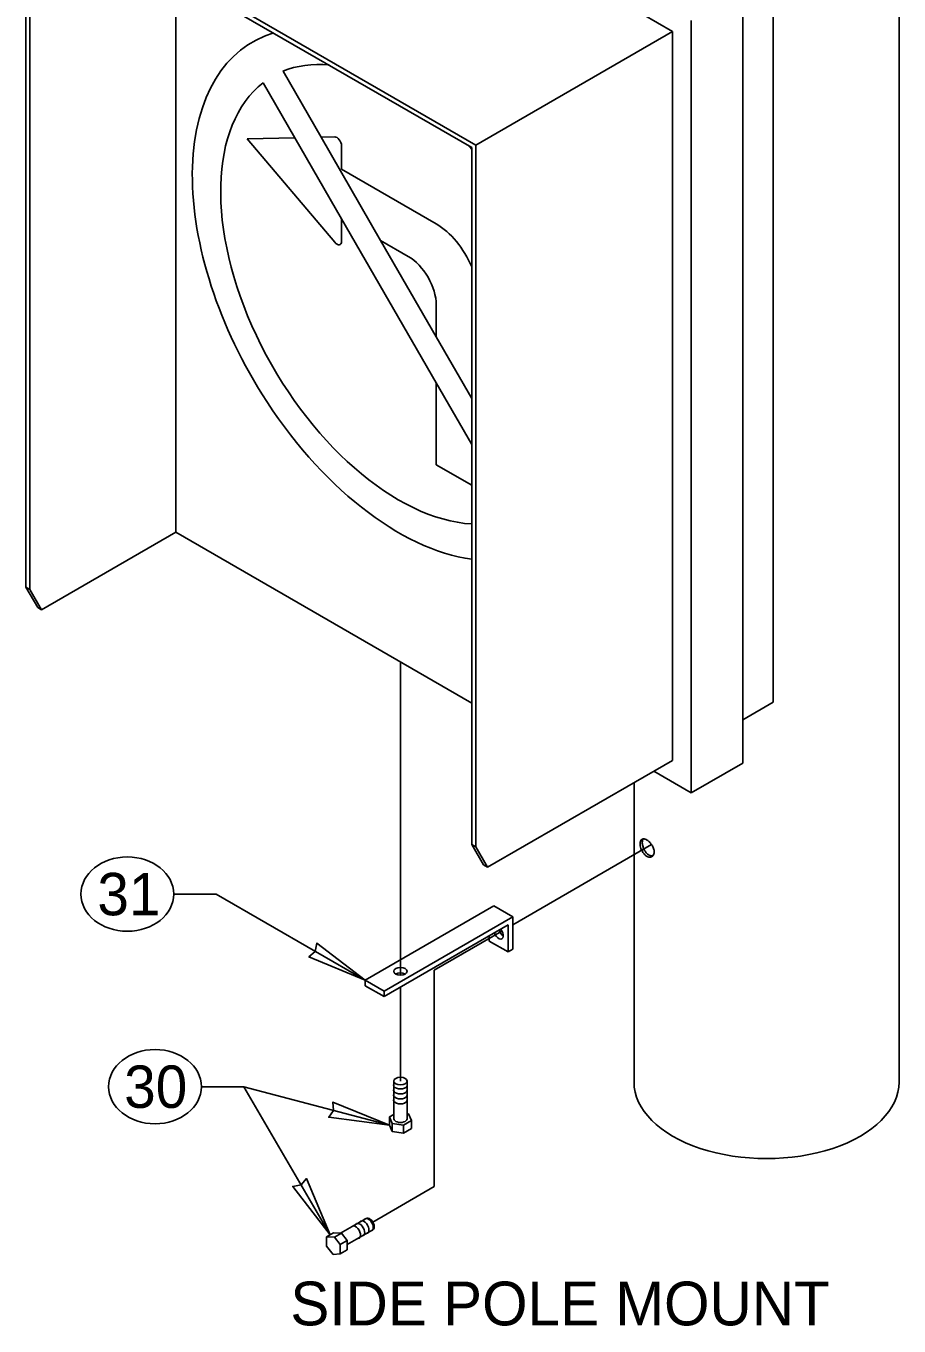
# Model space of a CAD drawing. Extents: x 99862 to 104211, y 98939 to 102076.
# Drawn here: x 101431.2 to 101760.6, y 100458.9 to 100949.2 of the extents above; entities that cross this region are included whole.
import ezdxf

# ---------------------------------------------------------------- set-up
doc = ezdxf.new("R2010")
doc.units = 0
for name, color, linetype in [('Level 1', 7, 'Continuous'), ('Level 12', 7, 'Continuous'), ('Level 15', 7, 'Continuous'), ('Level 20', 7, 'Continuous'), ('Level 22', 7, 'Continuous'), ('Level 27', 7, 'Continuous'), ('Level 31', 7, 'Continuous'), ('Level 32', 7, 'Continuous')]:
    doc.layers.add(name, color=color, linetype=linetype)

msp = doc.modelspace()

# ---------------------------------------------------------------- linework, layer by layer
at = {"layer": 'Level 1'}
msp.add_line((101663.6, 100642.46), (101663.6, 100642.46), dxfattribs=at)
for centre, major_axis in [((101572.46, 100549.79), (2.59, 0)), ((101572.46, 100547.92), (2.59, 0)), ((101572.46, 100546.05), (2.59, 0)), ((101572.46, 100544.17), (2.59, 0)), ((101557.16, 100495.22), (-1.29, 2.24)), ((101558.78, 100496.16), (-1.29, 2.24)), ((101560.41, 100497.1), (-1.29, 2.24)), ((101555.54, 100494.28), (-1.29, 2.24))]:
    msp.add_ellipse(centre, major_axis=major_axis, ratio=0.57735, start_param=2.878526, end_param=6.548134, dxfattribs=at)
for points in [[(101665.37, 100636.09), (101665.02, 100636.3), (101664.69, 100636.58), (101664.08, 100637.28), (101663.82, 100637.69), (101663.16, 100639.01), (101662.92, 100640), (101662.92, 100641.2), (101662.98, 100641.56), (101663.21, 100642.12), (101663.38, 100642.33), (101663.82, 100642.59), (101664.08, 100642.63), (101664.69, 100642.55), (101665.03, 100642.42), (101666.06, 100641.82), (101666.8, 100641.12), (101667.62, 100639.89), (101667.84, 100639.45), (101668.14, 100638.58), (101668.22, 100638.15), (101668.23, 100637.34), (101668.15, 100636.97), (101667.84, 100636.37), (101667.62, 100636.12), (101666.81, 100635.66), (101666.07, 100635.69), (101665.37, 100636.09)], [(101664.05, 100642.6), (101663.84, 100642.29), (101663.72, 100641.82), (101663.72, 100640.87), (101663.78, 100640.42), (101664, 100639.5), (101664.17, 100639.04), (101664.61, 100638.15), (101664.88, 100637.74), (101665.48, 100637.04), (101665.82, 100636.75), (101666.69, 100636.25), (101667.24, 100636.15), (101667.71, 100636.26)]]:
    msp.add_open_spline(points, degree=3, dxfattribs=at)
at = {"layer": 'Level 12'}
for p, q in [((101760.6, 100550.89), (101760.6, 101272.27)), ((101660.6, 100663.86), (101660.6, 100550.89))]:
    msp.add_line(p, q, dxfattribs=at)
msp.add_ellipse((101710.6, 100550.89), major_axis=(50, 0), ratio=0.57735, start_param=3.141583, end_param=6.283185, dxfattribs=at)
at = {"layer": 'Level 15'}
for p, q in [((101572.46, 100591.22), (101572.46, 100709.38)), ((101667.24, 100640.45), (101614.83, 100610.21)), ((101486.91, 100621.8), (101502.91, 100621.8)), ((101559.2, 100589.3), (101502.91, 100621.8)), ((101610.76, 100607.87), (101585.21, 100593.13)), ((101585.21, 100593.13), (101585.21, 100511.5)), ((101572.46, 100551.26), (101572.46, 100586.75)), ((101497.35, 100549.16), (101513.35, 100549.16)), ((101513.35, 100549.16), (101568.28, 100534.67)), ((101513.35, 100549.16), (101545.92, 100493.29)), ((101585.21, 100511.5), (101562.04, 100498.1))]:
    msp.add_line(p, q, dxfattribs=at)
for points in [[(101559.2, 100589.3), (101537.94, 100598.13), (101540.34, 100600.19), (101540.92, 100603.3)], [(101568.28, 100534.67), (101545.44, 100537.61), (101547.22, 100540.23), (101546.96, 100543.38)], [(101545.92, 100493.29), (101531.84, 100511.51), (101534.95, 100512.1), (101537, 100514.52)]]:
    msp.add_lwpolyline(points, close=True, dxfattribs=at)
at = {"layer": 'Level 20'}
for centre in [(101469.41, 100621.8), (101479.85, 100549.16)]:
    msp.add_ellipse(centre, major_axis=(-17.5, 0), ratio=0.8, dxfattribs=at)
at = {"layer": 'Level 22'}
for p, q in [((101431.16, 101002.31), (101431.16, 100737.57)), ((101600.87, 100904.33), (101431.16, 101002.31)), ((101675.12, 100947.2), (101575.94, 101004.46)), ((101432.66, 100736.7), (101432.66, 100999.71)), ((101599.37, 100903.46), (101432.66, 100999.71)), ((101713.13, 100694.19), (101713.13, 100969.14)), ((101487.74, 100967.91), (101487.74, 100758.29)), ((101701.64, 100671.23), (101701.64, 100962.51)), ((101682.2, 100660), (101682.2, 100951.28)), ((101600.87, 100904.33), (101675.12, 100947.2)), ((101675.12, 100947.2), (101675.12, 100672.25)), ((101600.87, 100639.59), (101600.87, 100904.33)), ((101599.37, 100640.45), (101599.37, 100903.46)), ((101437.08, 100729.05), (101487.74, 100758.29)), ((101487.74, 100758.29), (101599.37, 100693.84)), ((101431.16, 100737.57), (101435.58, 100729.91)), ((101431.16, 100737.57), (101432.66, 100736.7)), ((101432.66, 100736.7), (101437.08, 100729.05)), ((101435.58, 100729.91), (101437.08, 100729.05)), ((101701.64, 100687.56), (101713.13, 100694.19)), ((101605.29, 100631.93), (101675.12, 100672.25)), ((101682.2, 100660), (101701.64, 100671.23)), ((101668.05, 100668.17), (101682.2, 100660)), ((101599.37, 100640.45), (101603.79, 100632.8)), ((101599.37, 100640.45), (101600.87, 100639.59)), ((101600.87, 100639.59), (101605.29, 100631.93)), ((101603.79, 100632.8), (101605.29, 100631.93))]:
    msp.add_line(p, q, dxfattribs=at)
at = {"layer": 'Level 27'}
for p, q in [((101542.57, 100907.34), (101528.2, 100932.22)), ((101520.61, 100927.85), (101532.61, 100907.06)), ((101532.61, 100907.06), (101514.59, 100906.63)), ((101514.59, 100906.63), (101547.67, 100867.66)), ((101550.25, 100876.51), (101532.61, 100907.06)), ((101547.67, 100907.42), (101542.57, 100907.34)), ((101564.95, 100868.37), (101542.57, 100907.34)), ((101550.25, 100895.23), (101550.25, 100904.11)), ((101585.97, 100874.6), (101550.25, 100895.23)), ((101550.25, 100867.97), (101550.25, 100876.51)), ((101550.25, 100876.51), (101585.97, 100814.63)), ((101586.06, 100874.66), (101585.97, 100874.6)), ((101549.73, 100866.83), (101549.82, 100866.88)), ((101585.97, 100831.95), (101564.95, 100868.37)), ((101564.95, 100868.37), (101575.37, 100862.36)), ((101585.97, 100843.99), (101585.97, 100831.95)), ((101599.37, 100808.75), (101585.97, 100831.95)), ((101599.37, 100791.43), (101585.97, 100814.64)), ((101585.97, 100814.63), (101585.97, 100783.75)), ((101585.97, 100783.75), (101599.37, 100776.02))]:
    msp.add_line(p, q, dxfattribs=at)
for centre, major_axis, start_param, end_param in [((101571.71, 100848), (55, -95.26), 3.007404, 4.773824), ((101571.71, 100848), (-47.5, 82.27), 5.898115, 6.204156), ((101571.8, 100848.05), (-47.5, 82.27), 0.080896, 2.779139), ((101548.48, 100905.13), (-1.25, 2.17), 3.926991, 5.977732), ((101571.71, 100848), (-47.5, 82.27), 5.073399, 5.097459), ((101585.97, 100856.23), (-11.25, 19.49), 4.496649, 5.497787), ((101548.48, 100868.99), (-1.25, 2.17), 1.87625, 3.926991), ((101575.37, 100850.11), (-7.5, 12.99), 3.926991, 5.497787), ((101571.71, 100848), (55, -95.26), 4.773824, 5.861358)]:
    msp.add_ellipse(centre, major_axis=major_axis, ratio=0.57735, start_param=start_param, end_param=end_param, dxfattribs=at)
at = {"layer": 'Level 31'}
for p, q in [((101566.27, 100585.22), (101614.83, 100613.25)), ((101613.06, 100599.99), (101613.06, 100610.19)), ((101569.96, 100551.26), (101569.96, 100537.09)), ((101574.96, 100537.09), (101574.96, 100551.26)), ((101569.96, 100538.71), (101568.28, 100537.74)), ((101568.28, 100534.67), (101568.28, 100537.74)), ((101568.28, 100537.74), (101569.4, 100535.32)), ((101573.58, 100534.67), (101576.64, 100536.44)), ((101575.52, 100538.86), (101574.96, 100538.94)), ((101576.64, 100536.44), (101575.52, 100538.86)), ((101576.64, 100533.38), (101576.64, 100536.44)), ((101568.28, 100534.67), (101569.4, 100532.26)), ((101569.4, 100532.26), (101569.4, 100535.32)), ((101569.4, 100535.32), (101573.58, 100534.67)), ((101569.4, 100532.26), (101573.58, 100531.61)), ((101573.58, 100531.61), (101573.58, 100534.67)), ((101573.58, 100531.61), (101576.64, 100533.38)), ((101549.86, 100493.89), (101559.5, 100499.45)), ((101544.59, 100492.53), (101547.25, 100494.06)), ((101544.59, 100492.53), (101544.59, 100488.99)), ((101547.59, 100492.34), (101544.59, 100492.53)), ((101550.24, 100493.87), (101547.25, 100494.06)), ((101547.59, 100492.34), (101550.24, 100493.87)), ((101547.59, 100492.34), (101549.75, 100489.65)), ((101550.24, 100493.87), (101552.4, 100491.18)), ((101552.4, 100489.59), (101562.07, 100495.17)), ((101547.1, 100485.88), (101544.59, 100488.99)), ((101549.75, 100489.65), (101552.4, 100491.18)), ((101549.75, 100489.65), (101549.75, 100486.11)), ((101549.75, 100486.11), (101552.4, 100487.65)), ((101552.4, 100491.18), (101552.4, 100487.65)), ((101549.75, 100486.11), (101547.1, 100485.88))]:
    msp.add_line(p, q, dxfattribs=at)
msp.add_ellipse((101572.46, 100551.26), major_axis=(-2.5, 0), ratio=0.57735, dxfattribs=at)
for centre, major_axis, start_param, end_param in [((101572.46, 100537.09), (-2.5, 0), 6.283185, 9.424778), ((101560.82, 100497.33), (-1.25, 2.17), 3.141593, 6.341208)]:
    msp.add_ellipse(centre, major_axis=major_axis, ratio=0.57735, start_param=start_param, end_param=end_param, dxfattribs=at)
at = {"layer": 'Level 32'}
for p, q in [((101559.2, 100589.3), (101607.76, 100617.34)), ((101607.76, 100617.34), (101614.83, 100613.25)), ((101613.06, 100610.19), (101566.27, 100583.18)), ((101614.83, 100613.25), (101614.83, 100601.01)), ((101605.99, 100604.07), (101605.99, 100606.11)), ((101605.99, 100604.07), (101613.06, 100599.99)), ((101614.83, 100601.01), (101613.06, 100599.99)), ((101559.2, 100587.26), (101559.2, 100589.3)), ((101559.2, 100589.3), (101566.27, 100585.22)), ((101559.2, 100587.26), (101566.27, 100583.18)), ((101566.27, 100583.18), (101566.27, 100585.22))]:
    msp.add_line(p, q, dxfattribs=at)
for centre, major_axis, start_param, end_param in [((101609.52, 100607.13), (1.25, -2.17), 4.351022, 8.215349), ((101611.29, 100608.15), (-1.25, 2.17), 1.209429, 2.356194), ((101572.46, 100590.63), (2.5, 0), 0.785398, 2.356194)]:
    msp.add_ellipse(centre, major_axis=major_axis, ratio=0.57735, start_param=start_param, end_param=end_param, dxfattribs=at)
msp.add_ellipse((101572.46, 100592.67), major_axis=(-2.5, 0), ratio=0.57735, dxfattribs=at)

# ---------------------------------------------------------------- texts
at = {"layer": 'Level 20'}
for s, height, p in [('31', 16, (101458.09, 100613.8)), ('30', 16, (101468.22, 100541.16)), ('SIDE POLE MOUNT', 16.5, (101530.92, 100459.13))]:
    msp.add_text(s, height=height, dxfattribs=at).set_placement(p)

doc.saveas('drawing.dxf')
